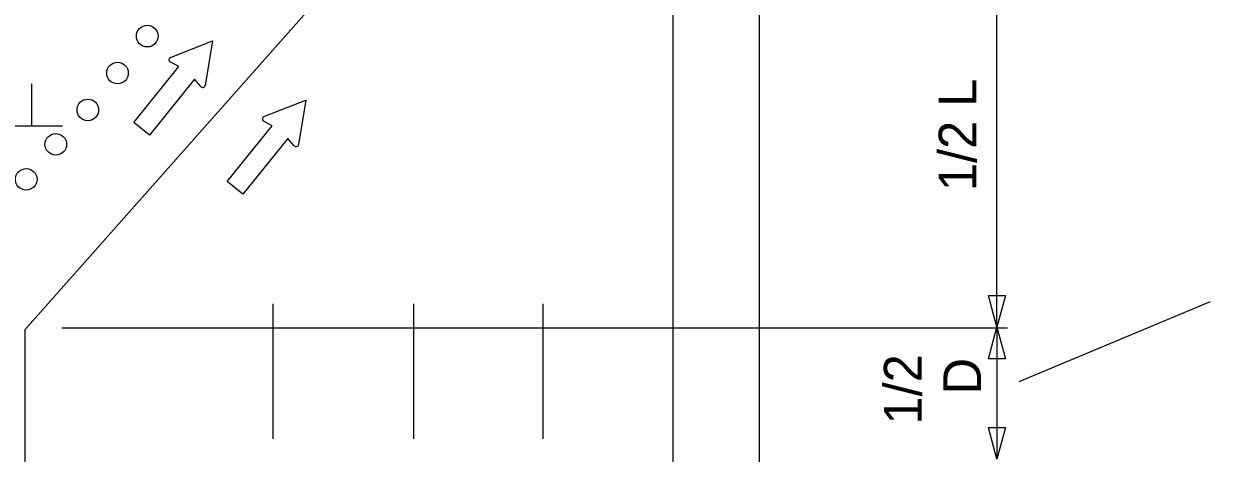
# Model space of a CAD drawing. Extents: x 16731 to 19504, y 5932 to 7446.
# Drawn here: x 17002.5 to 17222.2, y 6416.5 to 6495.9 of the extents above; entities that cross this region are included whole.
import ezdxf

# ---------------------------------------------------------------- set-up
doc = ezdxf.new("R2010")
doc.units = 0
for name, color, linetype in [('ALI_LEGAL_EX', 7, 'Continuous'), ('MT_SCRATCH_LEVEL_E', 7, 'Continuous'), ('PAVT_EDGE_EX', 7, 'Continuous'), ('TRAFFIC_SIGNS_PR', 7, 'Continuous'), ('TYPICAL_TEXT_DIMEN_PR', 7, 'Continuous')]:
    doc.layers.add(name, color=color, linetype=linetype)

msp = doc.modelspace()

# ---------------------------------------------------------------- linework, layer by layer
at = {"layer": 'ALI_LEGAL_EX'}
for points in [[(17048.71, 6419.12), (17048.71, 6444.12)], [(17074.71, 6419.12), (17074.71, 6444.12)], [(17098.71, 6419.12), (17098.71, 6444.12)]]:
    msp.add_lwpolyline(points, dxfattribs=at)
at = {"layer": 'MT_SCRATCH_LEVEL_E'}
for p, q in [((17029.66, 6489.71), (17037.44, 6492.75)), ((17029.66, 6489.71), (17037.44, 6492.75)), ((17037.44, 6492.75), (17036.1, 6484.53)), ((17037.44, 6492.75), (17036.1, 6484.53)), ((17031.19, 6488.01), (17029.61, 6488.88)), ((17031.19, 6488.01), (17029.61, 6488.88)), ((17022.88, 6477.68), (17031.19, 6488.01)), ((17022.88, 6477.68), (17031.19, 6488.01)), ((17034.1, 6485.66), (17025.79, 6475.33)), ((17034.1, 6485.66), (17025.79, 6475.33)), ((17035.29, 6484.3), (17034.1, 6485.66)), ((17035.29, 6484.3), (17034.1, 6485.66)), ((17046.96, 6478.77), (17054.73, 6481.8)), ((17046.96, 6478.77), (17054.73, 6481.8)), ((17054.73, 6481.8), (17053.39, 6473.59)), ((17054.73, 6481.8), (17053.39, 6473.59)), ((17048.49, 6477.06), (17046.91, 6477.93)), ((17048.49, 6477.06), (17046.91, 6477.93)), ((17025.79, 6475.33), (17022.88, 6477.68)), ((17025.79, 6475.33), (17022.88, 6477.68)), ((17040.17, 6466.74), (17048.49, 6477.06)), ((17040.17, 6466.74), (17048.49, 6477.06)), ((17051.4, 6474.72), (17043.09, 6464.39)), ((17051.4, 6474.72), (17043.09, 6464.39)), ((17052.59, 6473.36), (17051.4, 6474.72)), ((17052.59, 6473.36), (17051.4, 6474.72)), ((17043.09, 6464.39), (17040.17, 6466.74)), ((17043.09, 6464.39), (17040.17, 6466.74))]:
    msp.add_line(p, q, dxfattribs=at)
for centre, start, end in [((17029.84, 6489.28), 111.3861, 241.123), ((17029.84, 6489.28), 111.3861, 241.123), ((17035.64, 6484.61), 221.1954, 350.7344), ((17035.64, 6484.61), 221.1954, 350.7344), ((17047.14, 6478.33), 111.3861, 241.123), ((17047.14, 6478.33), 111.3861, 241.123), ((17052.94, 6473.67), 221.1954, 350.7344), ((17052.94, 6473.67), 221.1954, 350.7344)]:
    msp.add_arc(centre, 0.463, start, end, dxfattribs=at)
at = {"layer": 'PAVT_EDGE_EX'}
for p, q in [((17122.71, 6865.32), (17122.71, 6079.93)), ((17138.71, 6865.32), (17138.71, 6112.72)), ((17002.71, 6439.27), (17002.71, 6254.65))]:
    msp.add_line(p, q, dxfattribs=at)
at = {"layer": 'TRAFFIC_SIGNS_PR'}
for centre in [(17025.36, 6493.64), (17019.86, 6486.81), (17014.36, 6479.98), (17014.36, 6479.98), (17008.42, 6473.62), (17002.95, 6467.14)]:
    msp.add_circle(centre, 2, dxfattribs=at)
at = {"layer": 'TYPICAL_TEXT_DIMEN_PR'}
for p, q in [((17002.71, 6439.27), (17074.68, 6520.48)), ((17182.71, 6440.47), (17182.71, 6520.14)), ((17004.01, 6477.01), (17004.01, 6484.8)), ((17009.64, 6477.01), (16998.39, 6477.01)), ((17182.71, 6439.82), (17181.14, 6445.68)), ((17181.14, 6445.68), (17182.71, 6445.68)), ((17182.71, 6445.68), (17184.28, 6445.68)), ((17184.28, 6445.68), (17182.71, 6439.82)), ((17222.22, 6444.47), (17186.8, 6429.71)), ((17184.69, 6439.62), (17009.54, 6439.62)), ((17181.14, 6433.96), (17182.71, 6439.82)), ((17182.71, 6439.82), (17184.28, 6433.96)), ((17182.71, 6439.82), (17182.71, 6415.36)), ((17182.71, 6433.96), (17181.14, 6433.96)), ((17184.28, 6433.96), (17182.71, 6433.96)), ((17182.71, 6415.36), (17181.14, 6421.22)), ((17181.14, 6421.22), (17182.71, 6421.22)), ((17182.71, 6421.22), (17184.28, 6421.22)), ((17184.28, 6421.22), (17182.71, 6415.36))]:
    msp.add_line(p, q, dxfattribs=at)

# ---------------------------------------------------------------- texts
for s, p in [('1/2 L', (17178.93, 6464.96)), ('1/2', (17168.78, 6421.78)), ('D', (17179.78, 6427.35))]:
    msp.add_text(s, height=7, rotation=90, dxfattribs=at).set_placement(p)

doc.saveas('drawing.dxf')
